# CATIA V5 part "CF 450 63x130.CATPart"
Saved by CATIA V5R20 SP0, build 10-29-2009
Part number: CF 450 63x130
Definition: NONE
Nomenclature: CF 450 63x130
Source: Unknown
Description: CF 450 63x130
Bounding box of the stored display mesh (mm): x -46 to 46, y 0 to 130, z -46 to 46
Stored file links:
  C:\Users\Utente\Desktop\IO LAVORO\3D X SITO CF\X SITO\CF 450\CF 450 63x130.CATPart
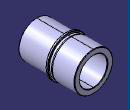
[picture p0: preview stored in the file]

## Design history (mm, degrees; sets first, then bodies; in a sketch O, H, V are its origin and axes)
Body1 "CF 450 63x130" (main body)
  Solid1: solid without history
